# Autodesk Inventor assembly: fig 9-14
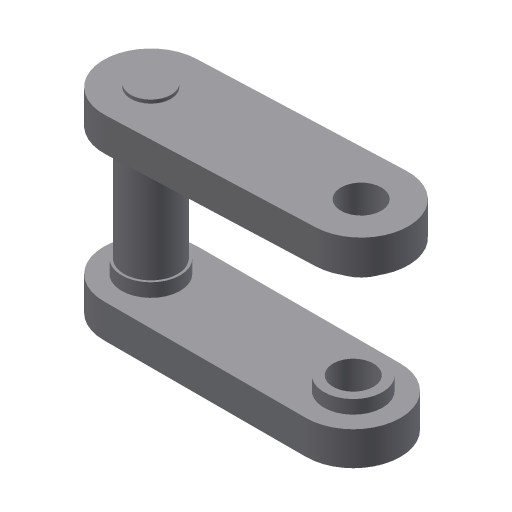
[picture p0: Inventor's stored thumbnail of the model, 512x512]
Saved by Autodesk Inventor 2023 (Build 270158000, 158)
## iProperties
Created: 2002-01
Part Number: fig 9-14
Document SubType Name: Assembly
Designer: ***
Control State: 0
Master: False
Checked Out: False
Shininess: 64.0
Length Units: 11269
Angle Units: 11279
Time Units: 11290
Mass Units: 11283
Length Display Precision: 3
Angle Display Precision: 2
Density: 0.0
Volumn: 0.0
Area: 0.0
PropertySet Name: Model Information
Author: ***
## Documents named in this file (3)
- D:\PROJECTS\Project 2022\Autodesk Inventor For Professional 2023\RESOURCES INVENTOR 2023\RESOURCES INVENTOR 2023\Inventor_2023_Part\Inventor_2023_Part\c09_Inv_2023_prt\fig 9-14.iam
- D:\PROJECTS\Project 2022\Autodesk Inventor For Professional 2023\RESOURCES INVENTOR 2023\RESOURCES INVENTOR 2023\Inventor_2023_Part\Inventor_2023_Part\c09_Inv_2023_prt\Part5.ipt
- D:\PROJECTS\Project 2022\Autodesk Inventor For Professional 2023\RESOURCES INVENTOR 2023\RESOURCES INVENTOR 2023\Inventor_2023_Part\Inventor_2023_Part\c09_Inv_2023_prt\Part6.ipt
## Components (3 placed, 2 different names)
1. Part5:1 — Insert:1
2. Part6:1 — Insert:1, Insert:2
3. Part5:2 — Insert:2
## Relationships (2: Insert 2)
- Insert:1: Part5:1 ↔ Part6:1
- Insert:2: Part6:1 ↔ Part5:2
